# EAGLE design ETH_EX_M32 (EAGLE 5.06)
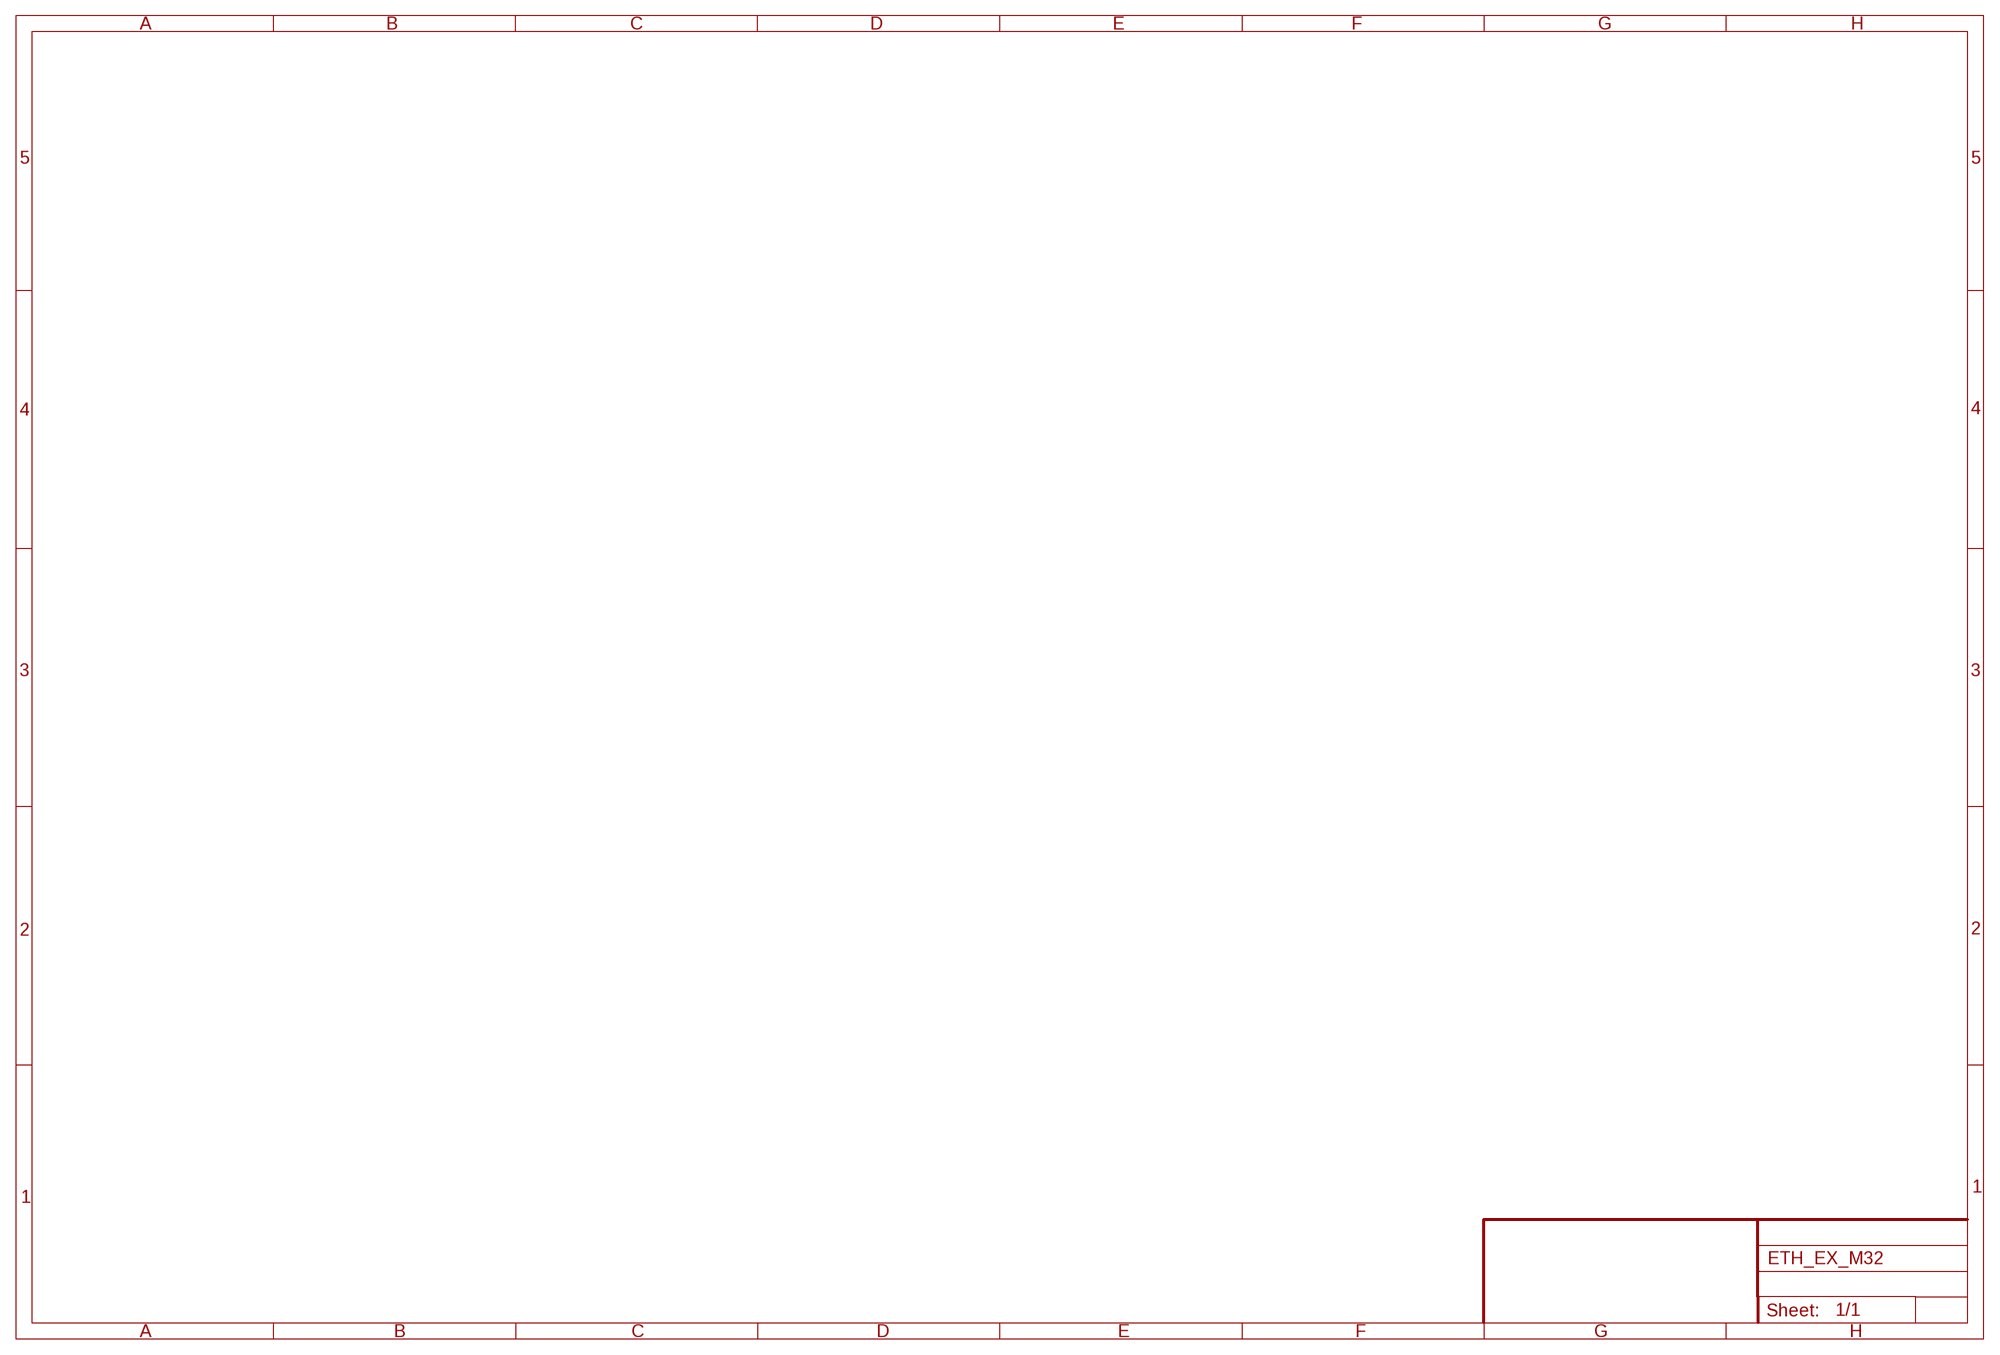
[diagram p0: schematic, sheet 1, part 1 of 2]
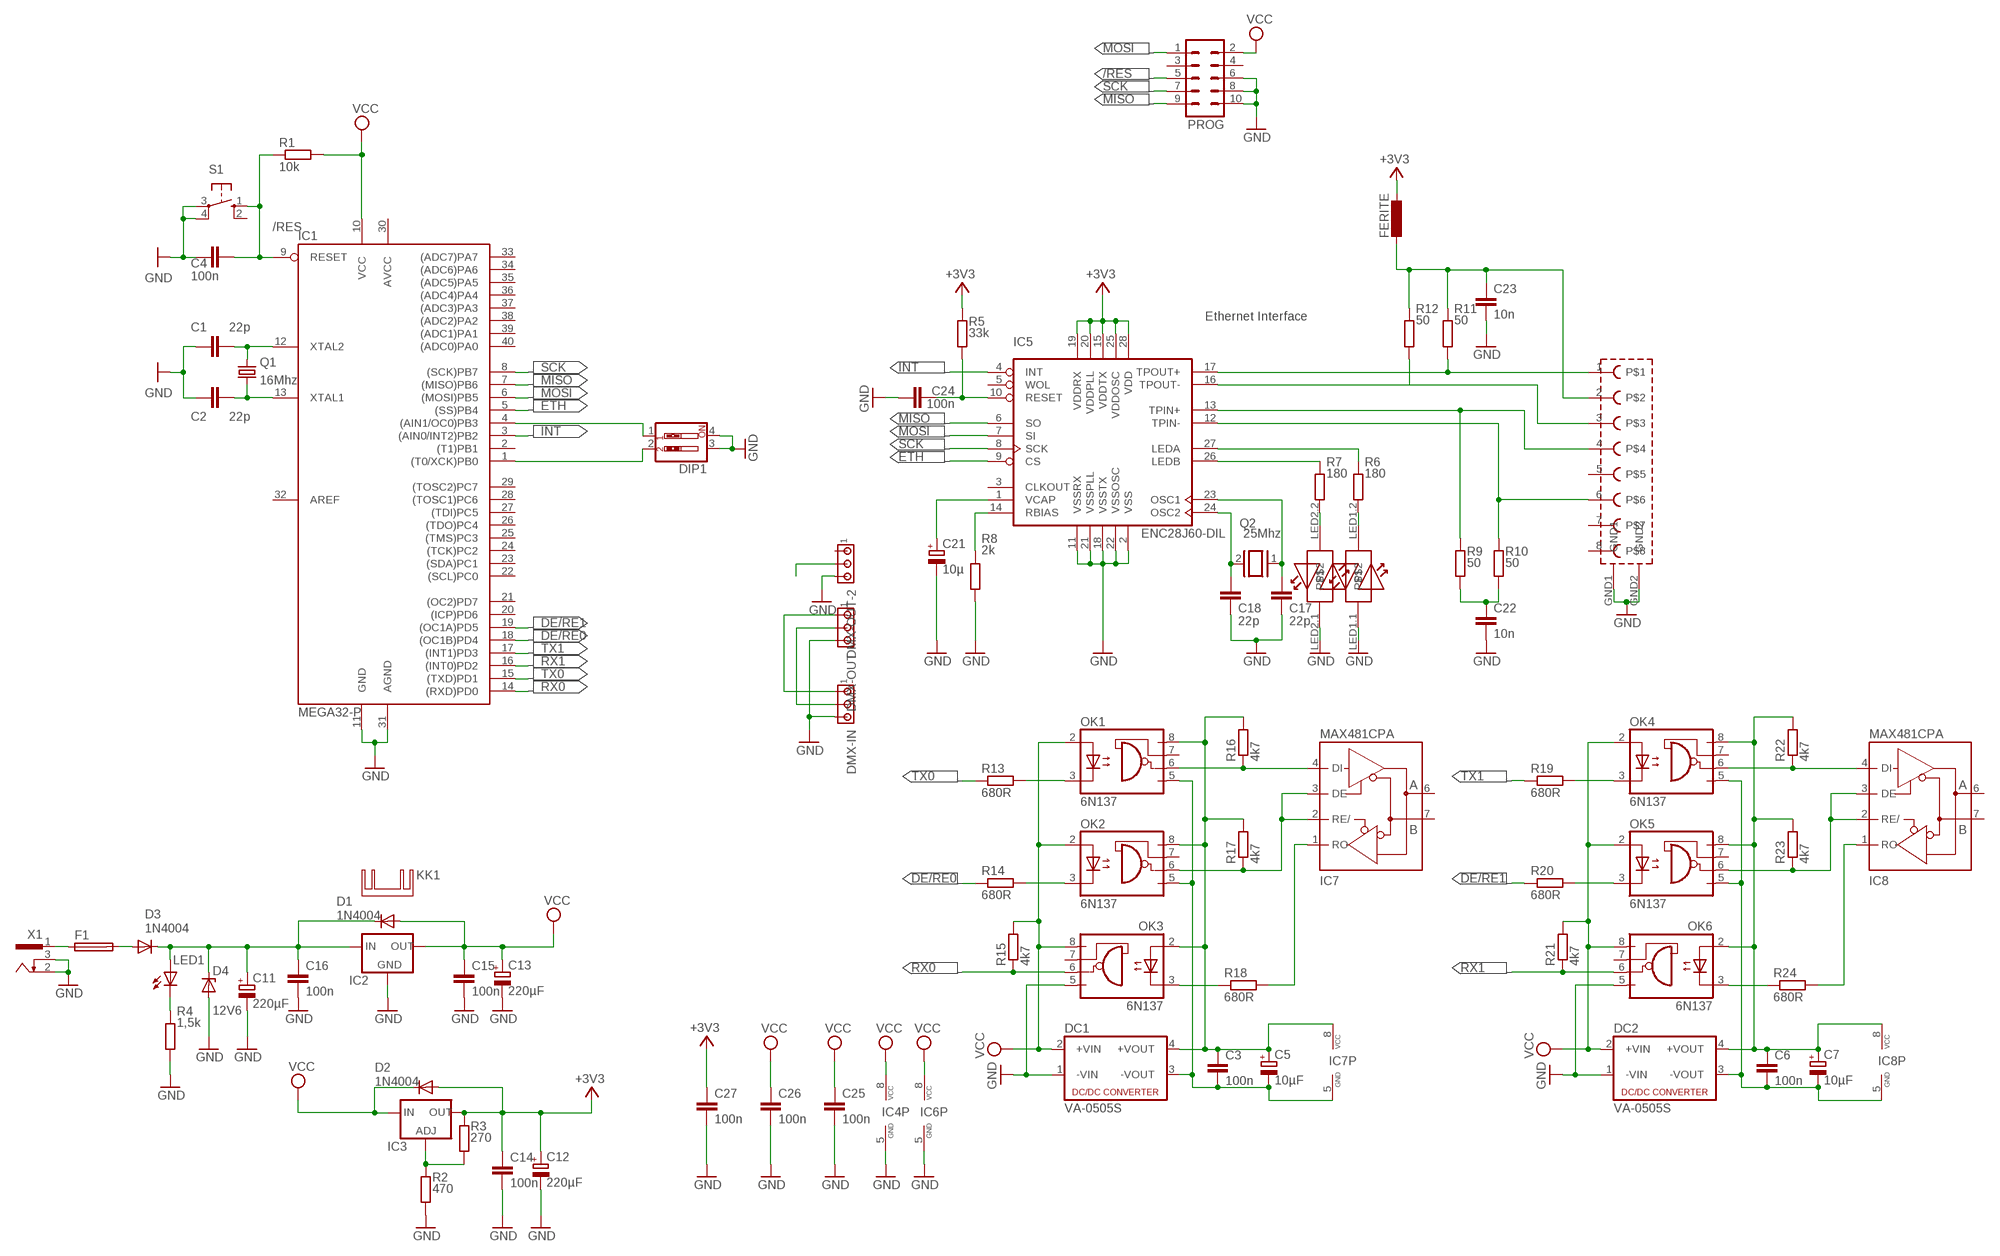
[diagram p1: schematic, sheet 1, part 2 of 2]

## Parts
C1  22p  C-EU025-024X044  [C025-024X044]
C2  22p  C-EU025-024X044  [C025-024X044]
C3  100n  C-EU025-025X050  [C025-025X050]
C4  100n  C-EU025-024X044  [C025-024X044]
C5  10µF  CPOL-EUE2-5  [E2-5]
C6  100n  C-EU025-025X050  [C025-025X050]
C7  10µF  CPOL-EUE2-5  [E2-5]
C11  220µF  CPOL-EUE3.5-8  [E3,5-8]
C12  220µF  CPOL-EUE3.5-8  [E3,5-8]
C13  220µF  CPOL-EUE3.5-8  [E3,5-8]
C14  100n  C-EU025-024X044  [C025-024X044]
C15  100n  C-EU050-024X044  [C050-024X044]
C16  100n  C-EU050-024X044  [C050-024X044]
C17  22p  C-EU025-024X044  [C025-024X044]
C18  22p  C-EU025-024X044  [C025-024X044]
C21  10µ  CPOL-EUE2-5  [E2-5]
C22  10n  C-EU025-025X050  [C025-025X050]
C23  10n  C-EU025-025X050  [C025-025X050]
C24  100n  C-EU025-024X044  [C025-024X044]
C25  100n  C-EU025-025X050  [C025-025X050]
C26  100n  C-EU025-025X050  [C025-025X050]
C27  100n  C-EU025-025X050  [C025-025X050]
D1  1N4004  [DO41-10]
D2  1N4004  [DO41-10]
D3  1N4004  [DO41-10]
D4  12V6  BZX90  [DO34Z7]
DC1  VA-0505S  [4SIL]
DC2  VA-0505S  [4SIL]
DIP1  SW_DIP-2  [EDG-02]
DMX-IN  MTA03-100  [10X03MTA]
DMX-OUT  MTA03-100  [10X03MTA]
DMX-OUT-2  MTA03-100  [10X03MTA]
F1  PICOFUSE  [PICOFUSE]
FERITE  L-EU0204/5  [0204/5]
IC1  MEGA32-P  [DIL40]
IC2  78XXS  [78XXS]
IC3  LM317TS  [317TS]
IC4  75176  MAX481CPA  [DIL08]
IC5  ENC28J60-DIL  [DIL28-3]
IC6  75176  MAX481CPA  [DIL08]
IC7  MAX481CPA  [DIL08]
IC8  MAX481CPA  [DIL08]
KK1  SK95-2M3  [SK95-2M3]
LED1  LED3MM  [LED3MM]
OK1  6N137  [DIL08]
OK2  6N137  [DIL08]
OK3  6N137  [DIL08]
OK4  6N137  [DIL08]
OK5  6N137  [DIL08]
OK6  6N137  [DIL08]
PROG  ML10  [ML10]
Q1  16Mhz  CRYTALHC49U-V  [HC49U-V]
Q2  25Mhz  XTAL/S  [QS]
R1  10k  R-EU_0207/10  [0207/10]
R2  470  R-EU_0207/10  [0207/10]
R3  270  R-EU_0207/10  [0207/10]
R4  1,5k  R-EU_0207/10  [0207/10]
R5  33k  R-EU_0207/10  [0207/10]
R6  180  R-EU_0207/10  [0207/10]
R7  180  R-EU_0207/10  [0207/10]
R8  2k  R-EU_0207/10  [0207/10]
R9  50  R-EU_0207/10  [0207/10]
R10  50  R-EU_0207/10  [0207/10]
R11  50  R-EU_0207/10  [0207/10]
R12  50  R-EU_0207/10  [0207/10]
R13  680R  R-EU_0207/7  [0207/7]
R14  680R  R-EU_0207/7  [0207/7]
R15  4k7  R-EU_0207/7  [0207/7]
R16  4k7  R-EU_0207/7  [0207/7]
R17  4k7  R-EU_0207/7  [0207/7]
R18  680R  R-EU_0207/7  [0207/7]
R19  680R  R-EU_0207/7  [0207/7]
R20  680R  R-EU_0207/7  [0207/7]
R21  4k7  R-EU_0207/7  [0207/7]
R22  4k7  R-EU_0207/7  [0207/7]
R23  4k7  R-EU_0207/7  [0207/7]
R24  680R  R-EU_0207/7  [0207/7]
S1  10-XX  [B3F-10XX]
U$1  MAGJACK  [MAGJACK]
X1  SCD-014A  [SCD-014-A]

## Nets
+3V3: C12.+ C14.1 C27.1 D2.A FERITE.1 IC3.2(OUT) IC5.15(VDDTX) IC5.19(VDDRX) IC5.20(VDDPLL) IC5.25(VDDOSC) IC5.28(VDD) R3.2 R5.2
/RES: C4.2 IC1.9(RESET) PROG.5 R1.1 S1.1(S)
DE/RE0: IC1.18((OC1B)PD4) R14.1
DE/RE1: IC1.19((OC1A)PD5) R20.1
ETH: IC1.5((SS)PB4) IC5.9(CS)
GND: C1.1 C2.1 C4.1 C11.- C12.- C13.- C14.2 C15.2 C16.2 C17.1 C18.1 C21.- C22.2 C23.2 C24.1 C25.1 C26.2 C27.2 D4.A DC1.1(-VIN) DC2.1(-VIN) DIP1.3 DIP1.4 DMX-IN.3 DMX-OUT-2.3 DMX-OUT.3 IC1.11(GND) IC1.31(AGND) IC2.GND IC4.5(GND) IC5.2(VSS) IC5.11(VSSRX) IC5.18(VSSTX) IC5.21(VSSPLL) IC5.22(VSSOSC) IC6.5(GND) OK3.5(GND) OK6.5(GND) PROG.6 PROG.8 PROG.10 R2.1 R4.1 R8.1 S1.3(P) S1.4(P1) U$1.GND1 U$1.GND2 U$1.LED1.1 U$1.LED2.1 X1.2 X1.3
INT: IC1.3((AIN0/INT2)PB2) IC5.4(INT)
MISO: IC1.7((MISO)PB6) IC5.6(SO) PROG.9
MOSI: IC1.6((MOSI)PB5) IC5.7(SI) PROG.1
N$1: C2.2 IC1.13(XTAL1) Q1.1
N$2: C1.2 IC1.12(XTAL2) Q1.2
N$4: LED1.K(C) R4.2
N$6: D3.A F1.2
N$8: R6.1 U$1.LED1.2
N$9: DIP1.2 IC1.1((T0/XCK)PB0)
N$10: F1.1 X1.1
N$11: IC5.27(LEDA) R6.2
N$12: IC3.1(ADJ) R2.2 R3.1
N$13: R7.1 U$1.LED2.2
N$14: IC5.26(LEDB) R7.2
N$18: DIP1.1 IC1.4((AIN1/OC0)PB3)
N$19: DMX-IN.1 DMX-OUT.1
N$20: C18.2 IC5.24(OSC2) Q2.2
N$21: C17.2 IC5.23(OSC1) Q2.1
N$22: IC5.12(TPIN-) R10.2 U$1.6
N$23: IC5.13(TPIN+) R9.2 U$1.4
N$24: IC5.16(TPOUT-) R12.2 U$1.3
N$25: IC5.17(TPOUT+) R11.2 U$1.1
N$26: IC5.14(RBIAS) R8.2
N$27: C21.+ IC5.1(VCAP)
N$28: DMX-IN.2 DMX-OUT.2
N$29: C22.1 R9.1 R10.1
N$30: C24.2 IC5.10(RESET) R5.1
N$32: DMX-OUT-2.2
N$34: C3.2 C5.- DC1.3(-VOUT) IC7.5(GND) OK1.5(GND) OK2.5(GND)
N$35: C3.1 C5.+ DC1.4(+VOUT) IC7.8(VCC) OK1.8(VCC) OK2.8(VCC) OK3.2(A) R16.2 R17.2
N$39: OK2.3(C) R14.2
N$40: OK1.3(C) R13.2
N$41: IC7.4(DI) OK1.6(VO) R16.1
N$42: IC7.2(RE/) IC7.3(DE) OK2.6(VO) R17.1
N$43: OK3.3(C) R18.1
N$44: IC7.1(RO) R18.2
N$45: C6.2 C7.- DC2.3(-VOUT) IC8.5(GND) OK4.5(GND) OK5.5(GND)
N$46: C6.1 C7.+ DC2.4(+VOUT) IC8.8(VCC) OK4.8(VCC) OK5.8(VCC) OK6.2(A) R22.2 R23.2
N$50: OK5.3(C) R20.2
N$51: OK4.3(C) R19.2
N$52: IC8.4(DI) OK4.6(VO) R22.1
N$53: IC8.2(RE/) IC8.3(DE) OK5.6(VO) R23.1
N$54: OK6.3(C) R24.1
N$55: IC8.1(RO) R24.2
N$248: C23.1 FERITE.2 R11.1 R12.1 U$1.2
N$250: C11.+ C16.1 D1.C D3.C D4.C IC2.IN LED1.A
RX0: IC1.14((RXD)PD0) OK3.6(VO) R15.1
RX1: IC1.16((INT0)PD2) OK6.6(VO) R21.1
SCK: IC1.8((SCK)PB7) IC5.8(SCK) PROG.7
TX0: IC1.15((TXD)PD1) R13.1
TX1: IC1.17((INT1)PD3) R19.1
VCC: C13.+ C15.1 C25.2 C26.1 D1.A D2.C DC1.2(+VIN) DC2.2(+VIN) IC1.10(VCC) IC2.OUT IC3.3(IN) IC4.8(VCC) IC6.8(VCC) OK1.2(A) OK2.2(A) OK3.8(VCC) OK4.2(A) OK5.2(A) OK6.8(VCC) PROG.2 R1.2 R15.2 R21.2
Unconnected: DMX-OUT-2.1 IC1.2((T1)PB1) IC1.20((ICP)PD6) IC1.21((OC2)PD7) IC1.22((SCL)PC0) IC1.23((SDA)PC1) IC1.24((TCK)PC2) IC1.25((TMS)PC3) IC1.26((TDO)PC4) IC1.27((TDI)PC5) IC1.28((TOSC1)PC6) IC1.29((TOSC2)PC7) IC1.33((ADC7)PA7) IC1.34((ADC6)PA6) IC1.35((ADC5)PA5) IC1.36((ADC4)PA4) IC1.37((ADC3)PA3) IC1.38((ADC2)PA2) IC1.39((ADC1)PA1) IC1.40((ADC0)PA0) IC4.1(RO) IC4.2(RE/) IC4.3(DE) IC4.4(DI) IC4.6(A) IC4.7(B) IC5.3(CLKOUT) IC5.5(WOL) IC6.1(RO) IC6.2(RE/) IC6.3(DE) IC6.4(DI) IC6.6(A) IC6.7(B) IC7.6(A) IC7.7(B) IC8.6(A) IC8.7(B) OK1.7(VE) OK2.7(VE) OK3.7(VE) OK4.7(VE) OK5.7(VE) OK6.7(VE) PROG.3 PROG.4 S1.2(S1) U$1.5 U$1.7 U$1.8

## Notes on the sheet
- Ethernet Interface

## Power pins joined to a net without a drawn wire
AREF: IC1.32(AREF)
AVCC: IC1.30(AVCC)

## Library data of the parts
C1 C2 C4 C14-C18 C22-C27 = rcl:C-EU: CAPACITOR, European symbol
C3 C6 = resistor:C-EU: CAPACITOR, European symbol
C5 C7 = resistor:CPOL-EU: POLARIZED CAPACITOR, European symbol
C11-C13 C21 = rcl:CPOL-EU: POLARIZED CAPACITOR, European symbol
D1-D3 = diode:1N4004: DIODE
D4 = diode:BZX90: Z DIODE
DC1 DC2 = dc-dc-converter:VA-*?: DC DC Converter Single Output, 1 Watt Motien Technology Co.,Ltd. Source: va-serie.pdf
DIP1 = special:SW_DIP-2: DIP SWITCH
DMX-IN DMX-OUT DMX-OUT-2 = con-amp:MTA03-100: AMP connector
F1 = fuse:PICOFUSE: PICOFUSE
FERITE = rcl:L-EU: INDUCTOR, European symbol
IC1 = avr-1:MEGA32-P: MICROCONTROLLER 32 Kbytes FLASH 2 Kbytes SRAM 1 Kbytes EEPROM USART 8-channel 10 bit ADC
IC2 = v-reg:78XXS: VOLTAGE REGULATOR
IC3 = v-reg:LM317TS: VOLTAGE REGULATOR
IC4 IC6-IC8 = maxim:MAX481CPA: RS485 TRANSEIVER
IC5 = enc28j60centered:ENC28J60-*: Microchip 10Mbit Ethernet controller with SPI interface Improved SOIC28 layout (pads in 0.01 raster, pin1 slightly smaller). Pin 6 (SO) changed from Out (paralleling several Outs gives an error) to OC. Author: Profi from mikrocontroller.net - forum Date: 2006.0827
KK1 = heatsink:SK95-2M3: HEATSINK
LED1 = led:LED: LED
OK1-OK6 = optocoupler:6N137: MOTOROLA OPTO COUPLER
PROG = con-harting-ml:ML10: HARTING
Q1 = crystal:CRYTAL: CRYSTAL
Q2 = special:XTAL/S: CRYSTAL
R1-R12 = rcl:R-EU_: RESISTOR, European symbol
R13-R24 = resistor:R-EU_: RESISTOR, European symbol
S1 = switch-omron:10-XX: OMRON SWITCH
U$1 = magjacksmalldrill:MAGJACK
X1 = con-shiua-chyuan:SCD-014A: Power Jack 2.5mm

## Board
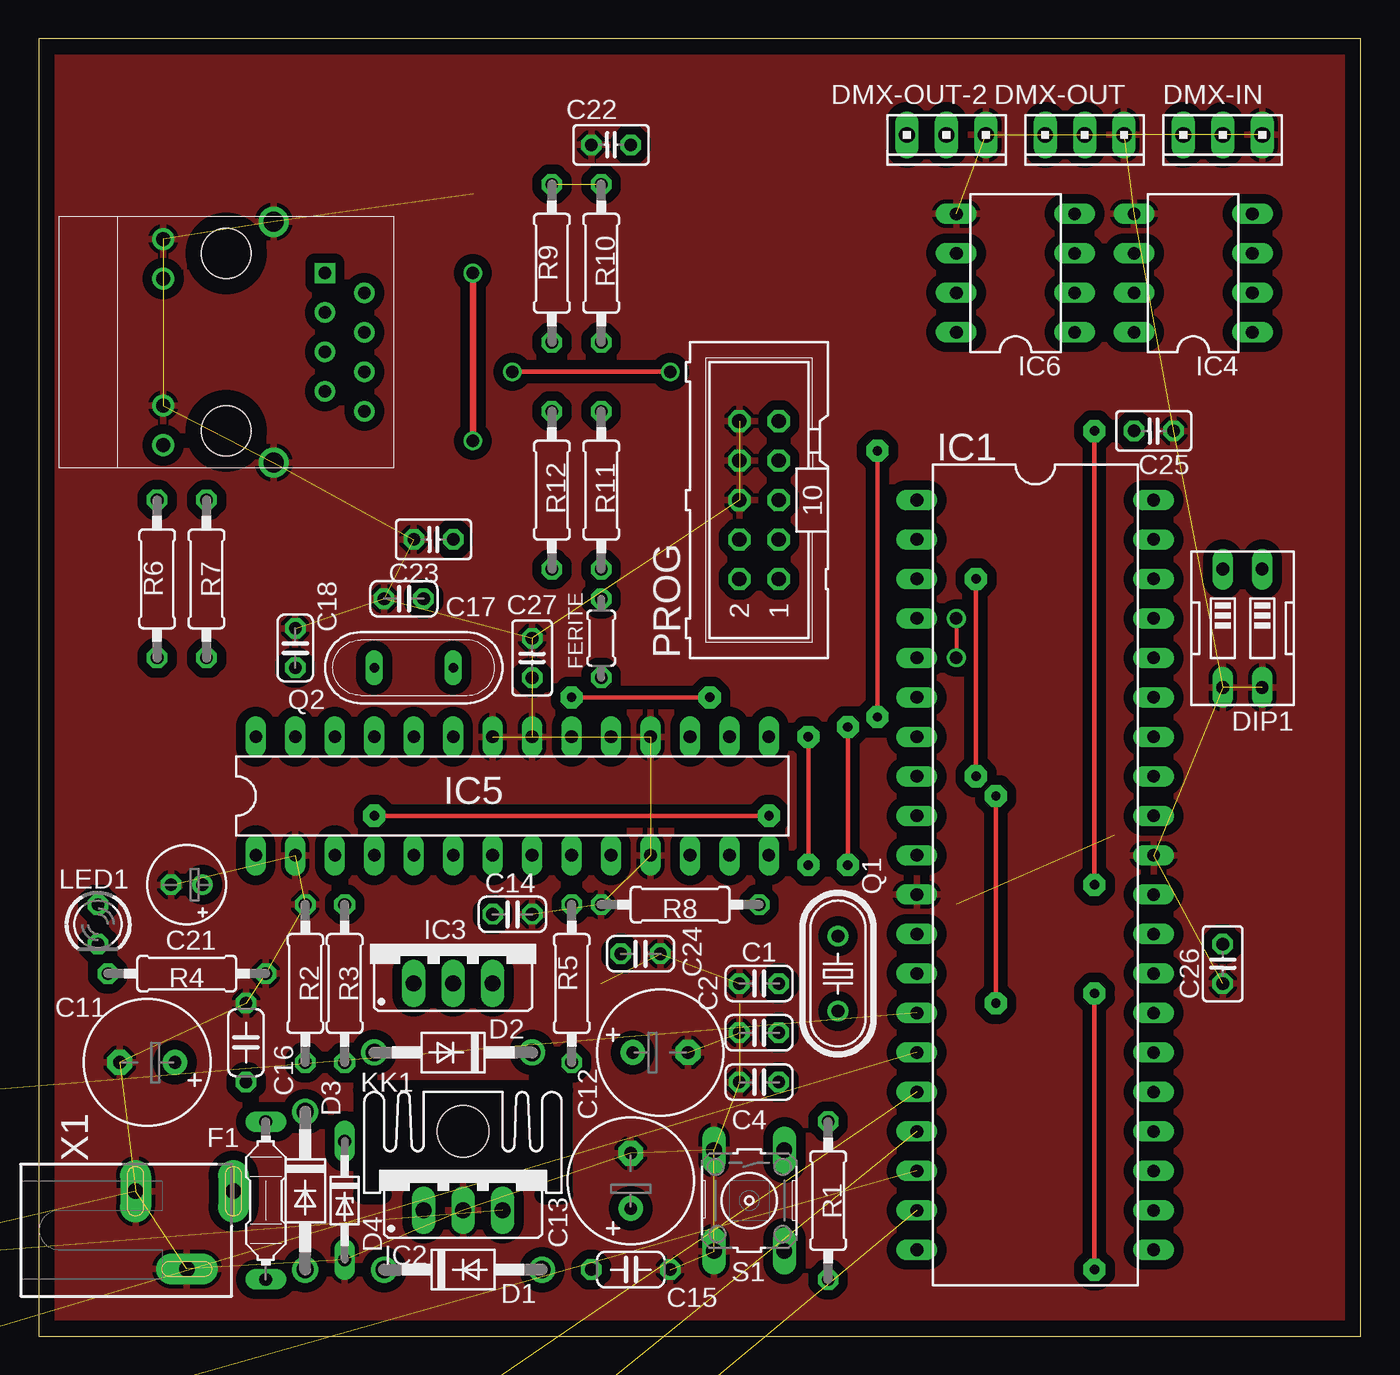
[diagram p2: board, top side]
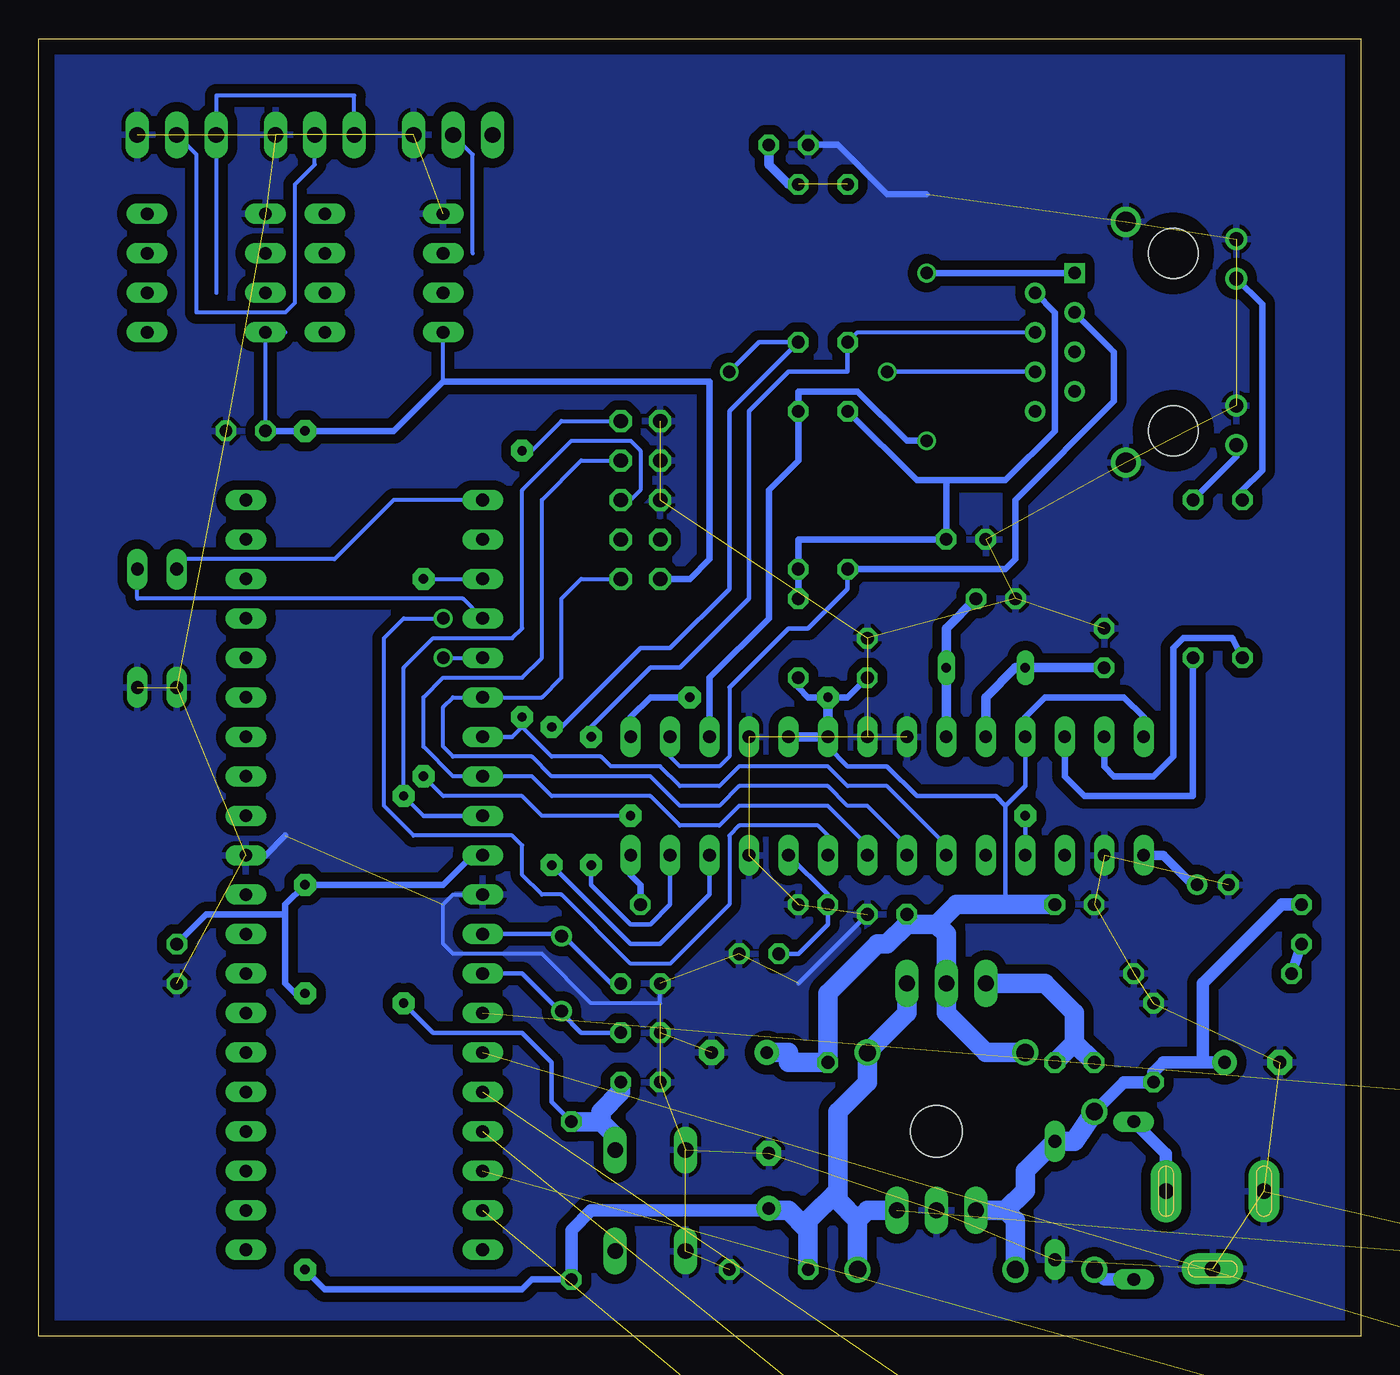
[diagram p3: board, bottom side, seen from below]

Size 85.07 x 83.49 mm. Coordinates in mm from the lower left corner, seen from the top.
Outline: 0,0 85.07,0 85.07,83.49 0,83.49 0,0
Copper layers (1*16): Top 0.035mm / dielectric 1.5mm / Bottom 0.035mm
Design rules "default": minimum track width 10mil, minimum drill 24mil, track to track 8mil, track to pad 8mil, pad to pad 8mil, via to via 8mil, smd to smd 8mil, copper to edge 40mil, drill to drill 8mil, minimum pad ring 10mil, minimum via ring 8mil, stop-mask expansion 4mil, vias tented up to drill 0mil, thermal gap 10mil

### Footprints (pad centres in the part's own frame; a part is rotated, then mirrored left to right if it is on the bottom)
C025-024X044 = drill 0.813 octagon: 1 -1.27,0; 2 1.27,0
C025-025X050 = drill 0.813 octagon: 1 -1.27,0; 2 1.27,0
E2-5 = drill 0.813 pad 1.27 round: + -1.016,0 | drill 0.813 pad 1.27 octagon: - 1.016,0
E3,5-8 = drill 0.813 pad 1.6 round: + -1.778,0 | drill 0.813 pad 1.6 octagon: - 1.778,0
C050-024X044 = drill 0.813 octagon: 1 -2.54,0; 2 2.54,0
DO41-10 = drill 1.118 round: A 5.08,0; C -5.08,0
DO34Z7 = drill 0.813 long: A 3.81,0; C -3.81,0
4SIL = drill 0.8 round: 1 -3.81,0; 2 -1.27,0; 3 1.27,0; 4 3.81,0
EDG-02 = drill 0.813 long: 1 -1.27,-3.81; 2 1.27,-3.81; 3 1.27,3.81; 4 -1.27,3.81
10X03MTA = drill 1.016 long: 1 2.54,0; 2 0,0; 3 -2.54,0
PICOFUSE = drill 0.813 long: 1 -5.08,0; 2 5.08,0
0204/5 = drill 0.813 octagon: 1 -2.54,0; 2 2.54,0
DIL40 = drill 0.813 long: 1 -24.13,-7.62; 2 -21.59,-7.62; 3 -19.05,-7.62; 4 -16.51,-7.62; 5 -13.97,-7.62; 6 -11.43,-7.62; 7 -8.89,-7.62; 8 -6.35,-7.62; 9 -3.81,-7.62; 10 -1.27,-7.62; 11 1.27,-7.62; 12 3.81,-7.62; 13 6.35,-7.62; 14 8.89,-7.62; 15 11.43,-7.62; 16 13.97,-7.62; 17 16.51,-7.62; 18 19.05,-7.62; 19 21.59,-7.62; 20 24.13,-7.62; 21 24.13,7.62; 22 21.59,7.62; 23 19.05,7.62; 24 16.51,7.62; 25 13.97,7.62; 26 11.43,7.62; 27 8.89,7.62; 28 6.35,7.62; 29 3.81,7.62; 30 1.27,7.62; 31 -1.27,7.62; 32 -3.81,7.62; 33 -6.35,7.62; 34 -8.89,7.62; 35 -11.43,7.62; 36 -13.97,7.62; 37 -16.51,7.62; 38 -19.05,7.62; 39 -21.59,7.62; 40 -24.13,7.62
78XXS = drill 1.016 long: GND 0,-2.54; IN -2.54,-2.54; OUT 2.54,-2.54
317TS = drill 1.016 long: 1 -2.54,-2.54; 2 0,-2.54; 3 2.54,-2.54
DIL08 = drill 0.813 long: 1 -3.81,-3.81; 2 -1.27,-3.81; 3 1.27,-3.81; 4 3.81,-3.81; 5 3.81,3.81; 6 1.27,3.81; 7 -1.27,3.81; 8 -3.81,3.81
DIL28-3 = drill 0.813 long: 1 -16.51,-3.81; 2 -13.97,-3.81; 3 -11.43,-3.81; 4 -8.89,-3.81; 5 -6.35,-3.81; 6 -3.81,-3.81; 7 -1.27,-3.81; 8 1.27,-3.81; 9 3.81,-3.81; 10 6.35,-3.81; 11 8.89,-3.81; 12 11.43,-3.81; 13 13.97,-3.81; 14 16.51,-3.81; 15 16.51,3.81; 16 13.97,3.81; 17 11.43,3.81; 18 8.89,3.81; 19 6.35,3.81; 20 3.81,3.81; 21 1.27,3.81; 22 -1.27,3.81; 23 -3.81,3.81; 24 -6.35,3.81; 25 -8.89,3.81; 26 -11.43,3.81; 27 -13.97,3.81; 28 -16.51,3.81
SK95-2M3 = hole 3.302: 0,2.54
LED3MM = drill 0.813 octagon: A -1.27,0; K 1.27,0
DIL08' = drill 0.813 offset: 1 -3.81,-3.81; 2 -1.27,-3.81; 3 1.27,-3.81; 4 3.81,-3.81; 5 3.81,3.81; 6 1.27,3.81; 7 -1.27,3.81; 8 -3.81,3.81
ML10 = drill 0.914 octagon: 1 -5.08,-1.27; 2 -5.08,1.27; 3 -2.54,-1.27; 4 -2.54,1.27; 5 0,-1.27; 6 0,1.27; 7 2.54,-1.27; 8 2.54,1.27; 9 5.08,-1.27; 10 5.08,1.27
HC49U-V = drill 0.813 round: 1 -2.413,0; 2 2.413,0
QS = drill 0.61 long: 1 -2.54,0; 2 2.54,0
0207/10 = drill 0.813 octagon: 1 -5.08,0; 2 5.08,0
0207/7 = drill 0.813 octagon: 1 -3.81,0; 2 3.81,0
B3F-10XX = drill 1.016 long: 1 -3.251,2.261; 2 3.251,2.261; 3 -3.251,-2.261; 4 3.251,-2.261
MAGJACK = drill 0.8 square: 1 -4.445,6.35 | drill 0.8 round: 2 -3.175,8.89; 3 -1.905,6.35; 4 -0.635,8.89; 5 0.635,6.35; 6 1.905,8.89; 7 3.175,6.35; 8 4.445,8.89 | drill 1.3 round: GND1 -7.747,3.048; GND2 7.747,3.048 | drill 0.9 round: LED1.1 -6.629,-4.064; LED1.2 -4.089,-4.064; LED2.1 4.089,-4.064; LED2.2 6.629,-4.064 | hole 3.2: -5.715,0; 5.715,0
SCD-014-A = drill 1 pad 2 long: 1 -2.5,13.8; 2 -2.5,7.5; 3 2.5,10.8

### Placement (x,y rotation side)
C1  46.35,22.7 0 top
C2  46.35,19.52 0 top
C3  not placed on the board
C4  46.35,16.35 0 top
C5  not placed on the board
C6  not placed on the board
C7  not placed on the board
C11  6.98,17.62 180 top
C12  40,18.25 0 top
C13  38.09,10 90 top
C14  30.48,27.14 0 top
C15  38.09,4.28 0 top
C16  13.33,18.89 90 top
C17  23.49,47.46 0 top
C18  16.51,44.29 270 top
C21  9.52,29.05 180 top
C22  36.82,76.67 180 top
C23  25.39,51.27 180 top
C24  38.73,24.6 180 top
C25  71.75,58.26 180 top
C26  76.2,23.96 270 top
C27  31.75,43.65 90 top
D1  27.3,4.28 0 top
D2  26.67,18.25 180 top
D3  17.14,9.36 270 top
D4  19.68,8.73 270 top
DC1  not placed on the board
DC2  not placed on the board
DIP1  77.47,45.55 180 top
DMX-IN  76.2,77.3 180 top
DMX-OUT  67.31,77.3 180 top
DMX-OUT-2  58.41,77.3 180 top
F1  14.6,8.73 270 top
FERITE  36.19,44.92 90 top
IC1  64.13,29.68 270 top
IC2  27.3,10.63 0 top
IC3  26.67,25.23 0 top
IC4  74.29,68.41 90 top
IC5  30.48,34.76 0 top
IC6  62.86,68.41 90 top
IC7  not placed on the board
IC8  not placed on the board
KK1  27.3,10.63 0 top
LED1  3.81,26.51 270 top
OK1  6N137  [DIL08']  not placed on the board
OK2  6N137  [DIL08']  not placed on the board
OK3  6N137  [DIL08']  not placed on the board
OK4  6N137  [DIL08']  not placed on the board
OK5  6N137  [DIL08']  not placed on the board
OK6  6N137  [DIL08']  not placed on the board
PROG  46.35,53.81 90 top
Q1  51.43,23.33 90 top
Q2  24.12,43.02 180 top
R1  50.79,8.73 270 top
R2  17.14,22.7 270 top
R3  19.68,22.7 90 top
R4  9.52,23.33 180 top
R5  34.28,22.7 270 top
R6  7.62,48.73 270 top
R7  10.79,48.73 270 top
R8  41.27,27.78 0 top
R9  33.02,69.05 270 top
R10  36.19,69.05 270 top
R11  36.19,54.45 90 top
R12  33.02,54.45 270 top
R13  not placed on the board
R14  not placed on the board
R15  not placed on the board
R16  not placed on the board
R17  not placed on the board
R18  not placed on the board
R19  not placed on the board
R20  not placed on the board
R21  not placed on the board
R22  not placed on the board
R23  not placed on the board
R24  not placed on the board
S1  45.71,8.73 270 top
U$1  12.06,63.97 270 top
X1  -1.27,6.82 270 top

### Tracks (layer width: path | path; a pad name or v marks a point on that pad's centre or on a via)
+3V3  (via drill 0.6 pad 1.42)
  Top 0.305: v34.28,41.11 v43.17,41.11
  Bottom 0.305: IC5.25 21.59,35.4 22.86,34.12 | IC5.20 34.28,37.94 33.02,36.66 30.48,36.66 28.57,34.76 23.49,34.76 22.86,34.12 | 22.86,27.78 22.86,34.12
  Bottom 0.406: IC5.28 13.96,39.84 15.23,41.11 20.32,41.11 21.59,39.84 IC5.25 | v43.17,41.11 45.71,41.11 46.98,39.84 IC5.15 | C27.1 33.02,41.11 v34.28,41.11 | v34.28,41.11 34.92,41.11 | v34.28,41.11 35.55,41.11 36.19,41.74 FERITE.1 | IC5.20 IC5.19 IC5.20
  Bottom 0.61: IC5.19 IC5.20 v34.28,41.11
  Bottom 1.27: C12.+ 36.82,18.25 36.82,17.62 R5.2 34.28,22.06 31.11,25.23 30.48,25.23 29.21,26.51 | D2.A 24.12,18.25 26.67,20.79 IC3.2 26.67,25.87 27.3,26.51 | 29.21,26.51 C14.1 | 27.3,26.51 29.21,26.51 | R3.2 22.86,27.78 26.03,27.78 27.3,26.51
/RES  (via drill 0.6 pad 1.42)
  Top 0.305: v61.59,21.43 v61.59,34.76
  Bottom 0.254: 60.32,33.49 v61.59,34.76 61.59,43.02 59.68,44.92 54.6,44.92 53.97,45.55 53.97,54.45 50.79,57.62 46.98,57.62 46.35,56.98 46.35,54.45 46.98,53.81 PROG.5
  Bottom 0.305: 48.89,14.44 R1.1 52.06,15.08 52.06,17.62 53.97,19.52 59.68,19.52 v61.59,21.43 | 60.32,33.49 IC1.9
  Bottom 1.27: S1.1 47.98,12.89 48.89,13.81 | 48.89,13.81 R1.1 | 48.89,13.81 48.89,14.44 47.62,15.71 C4.2
DE/RE0  (1 unrouted)
DE/RE1  (1 unrouted)
ETH  (via drill 0.8 pad 0.61)
  Top 0.254: v59.05,46.19 v59.05,43.65
  Bottom 0.254: IC5.9 34.28,32.22 34.92,32.86 40,32.86 40.63,32.22 40.63,27.78 44.45,23.96 46.98,23.96 51.43,28.41 52.7,28.41 53.97,29.68 53.97,31.59 54.6,32.22 60.95,32.22 62.86,34.12 62.86,44.92 61.59,46.19 v59.05,46.19 | v59.05,43.65 IC1.5
GND  (50 unrouted)
  Bottom 0.254: C1.1 45.08,21.43 49.52,21.43 52.7,24.6 58.41,24.6 59.05,25.23 59.05,27.78 58.41,28.41 IC1.11
  Bottom 0.305: C14.2 36.19,22.7
  Bottom 0.406: C22.2 33.65,76.67 30.48,73.49 27.94,73.49 | IC1.31 70.48,30.95 69.21,32.22
  pour Bottom (isolate 0.61): 0.63,83.02 0.63,0.47 84.45,0.47 84.45,83.02
  pour Top (isolate 0.61): 0.63,83.02 84.45,83.02 84.45,0.47 0.63,0.47
INT  (via drill 0.6 pad 1.42)
  Top 0.305: v21.59,33.49 v46.98,33.49 | v60.32,36.03 v60.32,48.73
  Bottom 0.254: v46.98,33.49 52.7,33.49 53.97,34.76 59.05,34.76 v60.32,36.03 | v60.32,48.73 IC1.3
  Bottom 0.305: IC5.4 v21.59,33.49
MISO  (via drill 0.6 pad 1.42)
  Top 0.305: v53.97,39.84 v53.97,56.98
  Bottom 0.254: IC5.6 26.67,31.59 30.48,35.4 33.02,35.4 34.28,36.66 40,36.66 41.27,35.4 43.81,35.4 45.08,36.66 48.25,36.66 48.89,37.3 52.06,37.3 53.97,39.2 | v53.97,56.98 53.34,56.98 51.43,58.89 PROG.9 | 53.97,39.2 v53.97,39.84 | 53.97,39.2 54.6,38.57
  Bottom 0.305: 54.6,38.57 IC1.7
MOSI
  Bottom 0.254: IC5.7 29.21,31.59 31.75,34.12 33.02,34.12 34.28,35.4 40,35.4 41.27,34.12 43.81,34.12 45.71,36.03 52.06,36.03 53.34,37.3 58.41,37.3 59.05,37.94 59.05,40.48 58.41,41.11 IC1.6 52.7,41.11 51.43,42.38 51.43,47.46 50.16,48.73 PROG.1
N$1
  Bottom 0.305: C2.2 50.16,19.52 51.43,20.79 | 51.43,20.79 Q1.1 | 51.43,20.79 53.97,23.33 IC1.13
N$2
  Bottom 0.305: C1.2 48.25,22.7 51.43,25.87 | 51.43,25.87 Q1.2 | 51.43,25.87 IC1.12
N$4
  Bottom 0.61: R4.2 LED1.K
N$6
  Bottom 0.813: F1.2 16.51,3.65 D3.A
N$8
  Bottom 0.406: R6.1 7.62,54.45 6.34,55.72 6.34,66.41 U$1.LED1.2
N$9
  Bottom 0.254: DIP1.2 76.2,50 66.04,50 62.22,53.81 IC1.1
N$10
  Bottom 0.813: X1.1 12.52,11.73 F1.1
N$11
  Bottom 0.406: IC5.27 16.51,36.66 15.87,36.03 13.33,36.03 12.06,37.3 12.06,44.29 11.42,44.92 8.25,44.92 R6.2
N$12
  Bottom 1.27: R2.2 18.41,18.89 | 18.41,18.89 R3.1 | 18.41,18.89 18.41,20.79 20.32,22.7 IC3.1
N$13
  Bottom 0.406: U$1.LED2.2 8,56.6 R7.1
N$14
  Bottom 0.406: IC5.26 19.05,36.03 17.78,34.76 11.42,34.76 10.79,34.76 R7.2
N$18
  Bottom 0.254: IC1.4 57.78,47.46 78.73,47.46 DIP1.1
N$19
  Bottom 0.254: 73.66,67.14 DMX-IN.1 73.66,79.84 64.77,79.84 DMX-OUT.1
N$20
  Bottom 0.61: IC5.24 24.12,41.11 22.22,43.02 Q2.2 C18.2
N$21
  Bottom 0.61: IC5.23 Q2.1 26.67,45.55 C17.2
N$22  (via drill 0.6 pad 1.42, 0.8)
  Top 0.305: v52.06,30.32 v52.06,39.2 | v40.63,62.06 v30.48,62.06
  Bottom 0.305: IC5.12 41.9,28.41 45.08,25.23 46.98,25.23 v52.06,30.32 | v52.06,39.2 51.43,39.2 46.35,44.29 44.45,44.29 40.63,48.09 40.63,59.52 R10.2 38.73,63.97 v40.63,62.06 | v30.48,62.06 U$1.6
N$23  (via drill 0.6 pad 1.42)
  Top 0.305: v49.52,30.32 v49.52,38.57
  Bottom 0.254: U$1.4 32.38,64.6 R9.2
  Bottom 0.305: IC5.13 44.45,27.78 45.71,26.51 46.98,26.51 49.52,29.05 v49.52,30.32 | v49.52,38.57 49.52,39.2 45.71,43.02 43.81,43.02 39.36,47.46 39.36,59.52 36.82,62.06 33.02,62.06 R9.2
N$24
  Bottom 0.254: IC5.16 44.45,37.3 43.81,36.66 41.27,36.66 40.63,37.3 40.63,41.74
  Bottom 0.305: 40.63,41.74 36.82,45.55 35.55,45.55 33.02,48.09 R12.2
  Bottom 0.406: R12.2 22.86,49.37 22.22,50 22.22,53.81 15.87,60.16 15.87,63.34 U$1.3
N$25  (via drill 0.8)
  Top 0.406: v27.94,57.62 v27.94,68.41
  Bottom 0.406: IC5.17 41.9,42.38 38.09,46.19 38.09,54.45 36.19,56.35 R11.2 36.19,60.8 32.38,60.8 29.21,57.62 v27.94,57.62 | v27.94,68.41 U$1.1
N$26
  Bottom 0.406: IC5.14 46.98,29.68 46.35,29.05 R8.2
N$27
  Bottom 0.61: C21.+ 10.79,29.05 12.69,30.95 IC5.1
N$28
  Bottom 0.254: DMX-OUT.2 67.31,75.4 68.58,74.13 68.58,69.68 68.58,66.51 69.21,65.88 74.93,65.88 74.93,76.03 DMX-IN.2
N$29  (1 unrouted)
  Bottom 0.61: R10.1 36.82,74.13 38.09,75.4 C22.1
N$30
  Bottom 0.305: IC5.10 34.28,28.41 R5.1 34.28,26.51 36.19,24.6 C24.2
N$32
  Bottom 0.254: 57.14,69.68 57.14,76.03 DMX-OUT-2.2
N$34  (5 unrouted)
N$35  (8 unrouted)
N$39  (1 unrouted)
N$40  (1 unrouted)
N$41  (2 unrouted)
N$42  (3 unrouted)
N$43  (1 unrouted)
N$44  (1 unrouted)
N$45  (5 unrouted)
N$46  (8 unrouted)
N$50  (1 unrouted)
N$51  (1 unrouted)
N$52  (2 unrouted)
N$53  (3 unrouted)
N$54  (1 unrouted)
N$55  (1 unrouted)
N$248
  Bottom 0.406: 26.67,55.08 C23.1 36.19,51.27 R11.1 FERITE.2 | U$1.2 19.68,65.88 19.68,58.26 22.86,55.08 26.67,55.08 | 26.67,55.08 28.57,55.08 R12.1
N$250
  Bottom 0.813: LED1.A 5.08,27.78 10.15,22.7 10.15,17.62 C11.+ 12.69,17.62 13.33,16.98 C16.1 15.23,16.35 D3.C
  Bottom 1.27: 22.86,8.09 21.59,9.36 21.59,10.63 D4.C 18.41,12.54 D3.C | 22.86,8.09 IC2.IN | D1.C 22.22,7.46 22.86,8.09
RX0  (2 unrouted)
RX1  (2 unrouted)
SCK
  Bottom 0.254: IC5.8 31.75,31.59 34.28,34.12 40,34.12 41.27,32.86 43.81,32.86 45.71,34.76 52.06,34.76 53.34,36.03 IC1.8 58.41,36.03 60.32,37.94 60.32,41.11 59.05,42.38 53.97,42.38 52.7,43.65 52.7,53.81 50.16,56.35 PROG.7
TX0  (1 unrouted)
TX1  (1 unrouted)
VCC  (via drill 0.6 pad 1.42)  (10 unrouted)
  Top 0.305: v67.94,4.28 v67.94,22.06 | v67.94,29.05 v67.94,58.26
  Bottom 0.254: C25.2 IC4.8 69.21,64.6 | 59.05,61.43 IC6.8
  Bottom 0.305: 57.14,30.95 IC1.10
  Bottom 0.406: 69.21,27.14 69.21,22.7 68.58,22.06 v67.94,22.06 | 69.21,27.14 69.21,27.78 v67.94,29.05 59.05,29.05 57.14,30.95 | v67.94,4.28 66.67,3.01 53.97,3.01 53.34,3.65 R1.2 | PROG.2 43.17,48.73 41.9,50 41.9,61.43 59.05,61.43 62.22,58.26 v67.94,58.26 C25.2 | 69.21,27.14 74.29,27.14 C26.1
  Bottom 0.813: 38.09,8.09 49.52,8.09 50.79,6.82 R1.2
  Bottom 1.27: IC2.OUT 31.75,8.09 32.38,7.46 | D1.A 32.38,7.46 | C13.+ 38.09,8.09 36.82,8.09 35.55,6.82 C15.1 35.55,7.46 33.65,9.36 33.65,8.73 | IC3.3 29.21,20.79 D2.C 31.75,16.35 33.65,14.44 33.65,8.73 | 32.38,7.46 33.65,8.73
